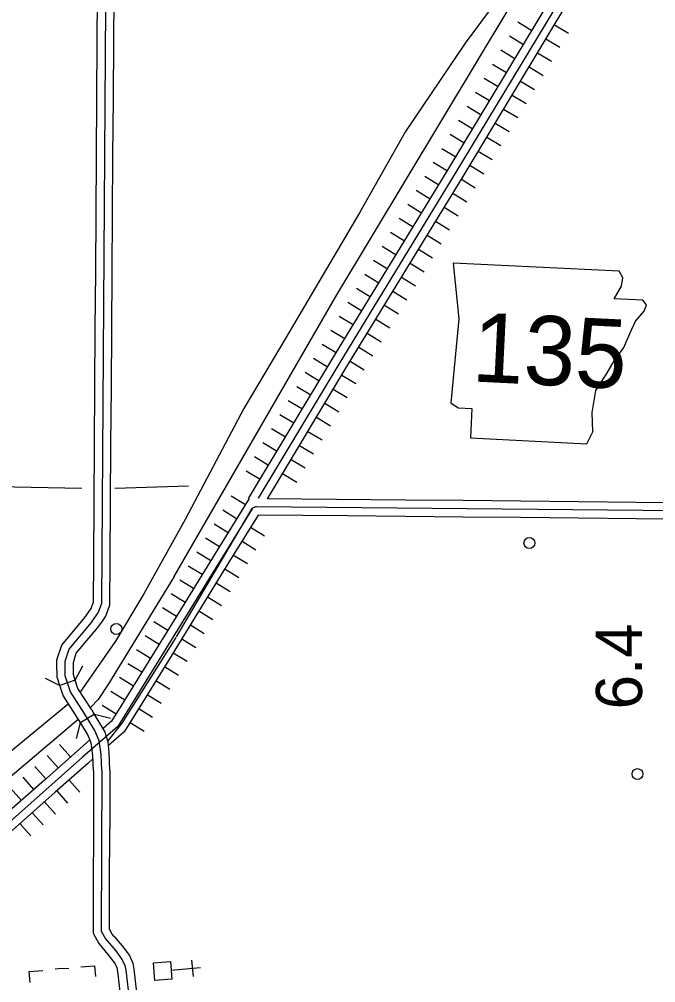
# Model space of a CAD drawing. Extents: x -4306 to 3843, y 131 to 8341.
# Drawn here: x -2104 to -1173, y 5516 to 6927 of the extents above; entities that cross this region are included whole.
import ezdxf

# ---------------------------------------------------------------- set-up
doc = ezdxf.new("R2010")
doc.units = 0
for name, color, linetype in [('21', 7, 'Continuous'), ('31', 7, 'Continuous'), ('32', 7, 'Continuous'), ('38', 7, 'Continuous'), ('46', 7, 'Continuous'), ('52', 7, 'Continuous'), ('56', 7, 'Continuous'), ('57', 7, 'Continuous'), ('58', 7, 'Continuous'), ('61', 7, 'Continuous'), ('63', 7, 'Continuous')]:
    doc.layers.add(name, color=color, linetype=linetype)

msp = doc.modelspace()

# ---------------------------------------------------------------- linework, layer by layer
at = {"layer": '21'}
msp.add_lwpolyline([(-1469.2, 6570), (-1461, 6488.3), (-1472.4, 6365.5), (-1461.9, 6358.2), (-1441.6, 6357.2), (-1443.8, 6314), (-1273.4, 6305.6), (-1264.4, 6322.8), (-1265.8, 6351.3), (-1260.1, 6383.6), (-1244, 6408.5), (-1233.6, 6427), (-1219.1, 6446.6), (-1209.9, 6467.9), (-1202.3, 6485.1), (-1189.4, 6499.4), (-1186.2, 6508.7), (-1191.3, 6515.7), (-1233.2, 6517.8), (-1222.8, 6536.2), (-1220.9, 6548.4), (-1226, 6558)], close=True, dxfattribs=at)
at = {"layer": '31'}
for p, q in [((-2022.2, 5959.2), (-2045, 5951.7)), ((-2018.3, 5947.4), (-2022.2, 5959.2)), ((-2040.1, 5936.9), (-2045, 5951.7)), ((-1998, 5916.1), (-2018.3, 5947.4)), ((-2018.3, 5903.4), (-2040.1, 5936.9)), ((-1995.9, 5912.6), (-1998, 5916.1)), ((-1979.1, 5884.4), (-1995.9, 5912.6)), ((-2016.5, 5900.3), (-2018.3, 5903.4)), ((-2004.5, 5880.1), (-2016.5, 5900.3)), ((-1994.1, 5909.4), (-2014.7, 5897.1)), ((-1974.2, 5868.6), (-1979.1, 5884.4)), ((-1999.1, 5867.4), (-2004.5, 5880.1)), ((-1972.7, 5854.1), (-1974.2, 5868.6)), ((-1996.5, 5849.2), (-1999.1, 5867.4)), ((-1971.5, 5827.4), (-1972.7, 5854.1)), ((-1995.5, 5826.4), (-1996.5, 5849.2)), ((-1995.5, 5827), (-1995.8, 5742.5)), ((-1971.5, 5826.9), (-1971.8, 5742.4)), ((-1971.8, 5742.4), (-1971.8, 5742.4)), ((-1965.3, 5584.1), (-1953.7, 5570.5)), ((-1983.6, 5568.6), (-1972.5, 5555.5)), ((-1953.7, 5570.5), (-1942.9, 5556.2)), ((-1972.5, 5555.5), (-1963.8, 5543.9)), ((-1963.8, 5543.9), (-1961.2, 5538.2)), ((-1942.9, 5556.2), (-1938, 5545.2)), ((-1938, 5545.2), (-1936.5, 5536.3)), ((-1961.2, 5538.2), (-1960.3, 5532.9)), ((-1960.3, 5532.9), (-1956.3, 5499)), ((-1936.5, 5536.3), (-1932.4, 5501.9))]:
    msp.add_line(p, q, dxfattribs=at)
for points in [[(-1995.8, 5742.5), (-1996, 5658)], [(-1972, 5657.9), (-1971.8, 5742.4)], [(-1996, 5658), (-1996.2, 5588.8), (-1987.9, 5573.7), (-1983.6, 5568.6)], [(-1965.3, 5584.1), (-1968, 5587.4), (-1972.2, 5595), (-1972, 5657.9)]]:
    msp.add_lwpolyline(points, dxfattribs=at)
at = {"layer": '32'}
for p, q in [((-1281.6, 7007.3), (-1466.4, 6700.5)), ((-1990, 6895.6), (-1989.4, 6980)), ((-1966, 6895.4), (-1965.4, 6979.9)), ((-1990.5, 6811.1), (-1990, 6895.6)), ((-1966.5, 6810.9), (-1966, 6895.4)), ((-1991.1, 6726.6), (-1990.5, 6811.1)), ((-1967.1, 6726.4), (-1966.5, 6810.9)), ((-1991.7, 6642.1), (-1991.1, 6726.6)), ((-1967.7, 6641.9), (-1967.1, 6726.4)), ((-1466.4, 6700.5), (-1634.9, 6424.7)), ((-1992.3, 6557.6), (-1991.7, 6642.1)), ((-1968.3, 6557.4), (-1967.7, 6641.9)), ((-1992.9, 6473.1), (-1992.3, 6557.6)), ((-1968.9, 6473), (-1968.3, 6557.4)), ((-1993.4, 6388.6), (-1992.9, 6473.1)), ((-1969.4, 6388.5), (-1968.9, 6473)), ((-1634.9, 6424.7), (-1754.5, 6225.6)), ((-1994, 6304.2), (-1993.4, 6388.6)), ((-1970, 6304), (-1969.4, 6388.5)), ((-1994.6, 6219.7), (-1994, 6304.2)), ((-1970.6, 6219.5), (-1970, 6304)), ((-1767.9, 6225.3), (-1817.7, 6144.6)), ((-1539, 6223), (-1740.8, 6225)), ((-1454.5, 6222.2), (-1539, 6223)), ((-1370.1, 6221.4), (-1454.5, 6222.2)), ((-1285.6, 6220.5), (-1370.1, 6221.4)), ((-1995.2, 6135.2), (-1994.6, 6219.7)), ((-1971.2, 6135), (-1970.6, 6219.5)), ((-1763.1, 6210.2), (-1959.8, 5891.5)), ((-1763.1, 6210.2), (-1959.8, 5891.5)), ((-1763.8, 6210.7), (-1874.4, 6022.8)), ((-1758.3, 6213), (-1763.8, 6210.7)), ((-1756.9, 6213.2), (-1758.3, 6213)), ((-271.9, 6198.6), (-1756.9, 6213.2)), ((-1201.1, 6219.7), (-1285.6, 6220.5)), ((-1116.6, 6218.9), (-1201.1, 6219.7)), ((-1754.6, 6201.1), (-1797.3, 6132)), ((-1623.8, 6199.9), (-1754.6, 6201.1)), ((-1539.3, 6199), (-1623.8, 6199.9)), ((-1454.8, 6198.2), (-1539.3, 6199)), ((-1370.3, 6197.4), (-1454.8, 6198.2)), ((-1285.8, 6196.5), (-1370.3, 6197.4)), ((-1201.3, 6195.7), (-1285.8, 6196.5)), ((-1116.8, 6194.9), (-1201.3, 6195.7)), ((-1817.7, 6144.6), (-1862.1, 6072.7)), ((-1995.6, 6074), (-1995.2, 6135.2)), ((-1971.6, 6069.8), (-1971.2, 6135)), ((-1797.3, 6132), (-1841.7, 6060.1)), ((-1999, 6064.4), (-1995.6, 6074)), ((-1977.5, 6053.3), (-1971.6, 6069.8)), ((-1862.1, 6072.7), (-1906.5, 6000.8)), ((-2008.2, 6051.2), (-2002.3, 6059.6)), ((-2002.3, 6059.6), (-1999, 6064.4)), ((-1982.6, 6045.9), (-1977.5, 6053.3)), ((-1841.7, 6060.1), (-1886, 5988.2)), ((-2042.1, 6010.7), (-2008.2, 6051.2)), ((-1989.1, 6036.6), (-1982.6, 6045.9)), ((-2020.7, 5998.9), (-1989.1, 6036.6)), ((-2049, 5989), (-2042.1, 6010.7)), ((-1875, 6021.7), (-1954.3, 5896.3)), ((-2025, 5985.3), (-2020.7, 5998.9)), ((-1906.5, 6000.8), (-1950.9, 5928.9)), ((-2049, 5982.9), (-2049, 5989)), ((-2048.9, 5963.7), (-2049, 5982.9)), ((-2025, 5983), (-2025, 5985.3)), ((-2024.9, 5967.6), (-2025, 5983)), ((-1886, 5988.2), (-1930.4, 5916.3)), ((-2022.2, 5959.2), (-2024.9, 5967.6)), ((-2045, 5951.7), (-2048.9, 5963.7)), ((-1950.9, 5928.9), (-1969.1, 5899.4)), ((-1930.4, 5916.3), (-1950.6, 5883.7)), ((-1969.1, 5899.4), (-1981.6, 5888.6)), ((-1954.3, 5896.3), (-1975.2, 5870.1)), ((-1959.8, 5891.5), (-2011.8, 5846.5)), ((-1959.8, 5891.5), (-2011.8, 5846.5)), ((-1950.6, 5883.7), (-1973.7, 5863.7)), ((-2001, 5871.8), (-2019.7, 5855.6)), ((-2019.7, 5855.6), (-2067.4, 5813.2)), ((-2011.8, 5846.5), (-2341.9, 5553.6)), ((-2011.8, 5846.5), (-2341.9, 5553.6)), ((-1996.3, 5844.1), (-2003.9, 5837.5)), ((-2003.9, 5837.5), (-2051.5, 5795.3)), ((-2067.4, 5813.2), (-2130.6, 5757.2)), ((-2051.5, 5795.3), (-2114.7, 5739.2))]:
    msp.add_line(p, q, dxfattribs=at)
for points in [[(-1983.6, 6071.9), (-1976.6, 7092.7)], [(-1983.5, 5826.9), (-1984.5, 5850.4), (-1987.5, 5870.6), (-1993.7, 5885.5), (-2008.1, 5909.8), (-2029.2, 5942.1), (-2036.9, 5965.7), (-2037, 5987.2), (-2031.4, 6004.8), (-1998.6, 6043.9), (-1988.2, 6058.8), (-1983.6, 6071.9)], [(-1983.5, 5826.9), (-1984.2, 5591.9), (-1978, 5580.6), (-1963.1, 5563), (-1953.4, 5550.1), (-1949.6, 5541.7), (-1948.4, 5534.6), (-1931.5, 5392.4), (-1927.1, 4704.6), (-1924.6, 4492.3), (-1929.1, 4070.4), (-1927.7, 3649.7), (-1928.3, 3227.1), (-1927.2, 3133.3)]]:
    msp.add_lwpolyline(points, dxfattribs=at)
at = {"layer": '38'}
for p, q in [((-2022.2, 5959.2), (-2011.4, 5980.6)), ((-2066.4, 5962.5), (-2045, 5951.7)), ((-2033.6, 5955.4), (-2033.6, 5955.4))]:
    msp.add_line(p, q, dxfattribs=at)
for points in [[(-2020.6, 5873.8), (-2014.7, 5897.1)], [(-1994.1, 5909.4), (-1970.8, 5903.5)]]:
    msp.add_lwpolyline(points, dxfattribs=at)
at = {"layer": '46'}
for p, q in [((-1476.6, 6706.8), (-1269.2, 7051.3)), ((-1456.1, 6694.3), (-1241.5, 7050.7)), ((-1645.2, 6430.9), (-1476.6, 6706.8)), ((-1624.7, 6418.4), (-1456.1, 6694.3)), ((-1768.7, 6225.3), (-1645.2, 6430.9)), ((-1740.8, 6225), (-1624.7, 6418.4))]:
    msp.add_line(p, q, dxfattribs=at)
at = {"layer": '52'}
for p, q in [((-2012.6, 6240.1), (-2463.1, 6248)), ((-1856.6, 6243.4), (-1964.4, 6240.1))]:
    msp.add_line(p, q, dxfattribs=at)
at = {"layer": '56'}
for points in [[(-1330.4, 7050.5), (-1406.5, 6952.3), (-1451.4, 6892.2), (-1538.8, 6762.8), (-1606.3, 6643.7), (-1713.9, 6460.4), (-1775.4, 6357), (-1861.2, 6194.6), (-1921.7, 6085.7), (-1963.4, 6016.6), (-2014.8, 5943)], [(-1877.3, 6111.1), (-1639.5, 6523.5), (-1385.4, 6945.6), (-1310.2, 7047.2)], [(-1877.3, 6111.1), (-1973.4, 5953.9), (-1988.6, 5931.1), (-1999.6, 5920)], [(-2398.5, 6031.6), (-2398.3, 6037), (-2395, 6040.1), (-2389.7, 6035.4), (-2388.7, 6026.5), (-2387.2, 6010.6), (-2387.6, 6008.6), (-2433.2, 5624.8), (-2429.8, 5610.9), (-2427.3, 5606.7), (-2422.5, 5606.4), (-2411.6, 5612.3), (-2032.7, 5924.6)], [(-2017.9, 5901.6), (-2420, 5561.3)]]:
    msp.add_lwpolyline(points, dxfattribs=at)
at = {"layer": '57'}
for centre in [(-1357.4, 6160.2), (-1962.1, 6034.3), (-1199.2, 5821.9)]:
    msp.add_circle(centre, 8, dxfattribs=at)
at = {"layer": '58'}
for p, q in [((-1852, 5549.2), (-1849.9, 5525.3)), ((-2041.8, 5537), (-2051.6, 5536.1)), ((-2041.8, 5537), (-2031.7, 5537.9)), ((-1839, 5538.3), (-1881.9, 5534.5))]:
    msp.add_line(p, q, dxfattribs=at)
msp.add_lwpolyline([(-1907.9, 5545.3), (-1883, 5547.5), (-1880.8, 5521.7), (-1905.6, 5519.5)], close=True, dxfattribs=at)
for points in [[(-2088.2, 5516.7), (-2089.6, 5532.7), (-2069.7, 5534.5)], [(-2013.9, 5539.5), (-1994, 5541.3), (-1992.6, 5525.3)]]:
    msp.add_lwpolyline(points, dxfattribs=at)
at = {"layer": '63'}
for p, q in [((-1374.4, 6923.1), (-1353.8, 6910.7)), ((-1320.9, 6918.9), (-1300.3, 6906.5)), ((-1386.8, 6902.5), (-1366.2, 6890.2)), ((-1386.8, 6902.5), (-1366.2, 6890.2)), ((-1333.2, 6898.3), (-1312.7, 6885.9)), ((-1399.1, 6882), (-1378.6, 6869.6)), ((-1345.6, 6877.8), (-1325.1, 6865.4)), ((-1345.6, 6877.8), (-1325.1, 6865.4)), ((-1411.5, 6861.4), (-1391, 6849)), ((-1358, 6857.2), (-1337.5, 6844.8)), ((-1423.9, 6840.9), (-1403.3, 6828.5)), ((-1423.9, 6840.9), (-1403.3, 6828.5)), ((-1370.4, 6836.6), (-1349.8, 6824.3)), ((-1436.3, 6820.3), (-1415.7, 6807.9)), ((-1382.8, 6816.1), (-1362.2, 6803.7)), ((-1382.8, 6816.1), (-1362.2, 6803.7)), ((-1448.7, 6799.7), (-1428.1, 6787.3)), ((-1395.2, 6795.5), (-1374.6, 6783.1)), ((-1461.1, 6779.2), (-1440.5, 6766.8)), ((-1461.1, 6779.2), (-1440.5, 6766.8)), ((-1407.5, 6775), (-1387, 6762.6)), ((-1473.4, 6758.6), (-1452.9, 6746.2)), ((-1419.9, 6754.4), (-1399.4, 6742)), ((-1419.9, 6754.4), (-1399.4, 6742)), ((-1485.8, 6738), (-1465.3, 6725.7)), ((-1432.3, 6733.8), (-1411.8, 6721.5)), ((-1498.1, 6717.7), (-1477.6, 6705.2)), ((-1498.1, 6717.7), (-1477.6, 6705.2)), ((-1444.7, 6713.3), (-1424.1, 6700.9)), ((-1510.6, 6697.2), (-1490.1, 6684.7)), ((-1457.1, 6692.7), (-1436.7, 6680.1)), ((-1457.1, 6692.7), (-1436.7, 6680.1)), ((-1523.1, 6676.7), (-1502.6, 6664.2)), ((-1469.6, 6672.2), (-1449.2, 6659.7)), ((-1535.6, 6656.2), (-1515.2, 6643.7)), ((-1535.6, 6656.2), (-1515.2, 6643.7)), ((-1482.2, 6651.7), (-1461.7, 6639.2)), ((-1548.2, 6635.8), (-1527.7, 6623.2)), ((-1494.7, 6631.2), (-1474.2, 6618.7)), ((-1494.7, 6631.2), (-1474.2, 6618.7)), ((-1560.7, 6615.3), (-1540.2, 6602.8)), ((-1507.2, 6610.7), (-1486.7, 6598.2)), ((-1573.2, 6594.8), (-1552.7, 6582.3)), ((-1573.2, 6594.8), (-1552.7, 6582.3)), ((-1519.7, 6590.2), (-1499.2, 6577.7)), ((-1585.7, 6574.3), (-1565.2, 6561.8)), ((-1532.2, 6569.8), (-1511.7, 6557.3)), ((-1532.2, 6569.8), (-1511.7, 6557.3)), ((-1598.2, 6553.8), (-1577.7, 6541.3)), ((-1544.7, 6549.3), (-1524.2, 6536.8)), ((-1610.7, 6533.3), (-1590.2, 6520.8)), ((-1610.7, 6533.3), (-1590.2, 6520.8)), ((-1557.2, 6528.8), (-1536.8, 6516.3)), ((-1623.2, 6512.9), (-1602.8, 6500.3)), ((-1569.8, 6508.3), (-1549.3, 6495.8)), ((-1569.8, 6508.3), (-1549.3, 6495.8)), ((-1635.8, 6492.4), (-1615.3, 6479.9)), ((-1582.3, 6487.8), (-1561.8, 6475.3)), ((-1648.3, 6471.9), (-1627.8, 6459.4)), ((-1648.3, 6471.9), (-1627.8, 6459.4)), ((-1594.8, 6467.4), (-1574.3, 6454.8)), ((-1660.8, 6451.4), (-1640.3, 6438.9)), ((-1607.3, 6446.9), (-1586.8, 6434.4)), ((-1607.3, 6446.9), (-1586.8, 6434.4)), ((-1673.3, 6430.6), (-1652.8, 6418.3)), ((-1619.8, 6426.4), (-1599.3, 6413.9)), ((-1685.7, 6410.1), (-1665.1, 6397.7)), ((-1685.7, 6410.1), (-1665.1, 6397.7)), ((-1632.2, 6405.9), (-1611.6, 6393.6)), ((-1698.1, 6389.5), (-1677.5, 6377.1)), ((-1644.5, 6385.3), (-1624, 6373)), ((-1644.5, 6385.3), (-1624, 6373)), ((-1710.4, 6368.9), (-1689.8, 6356.5)), ((-1656.9, 6364.8), (-1636.3, 6352.4)), ((-1722.8, 6348.3), (-1702.2, 6336)), ((-1722.8, 6348.3), (-1702.2, 6336)), ((-1669.3, 6344.2), (-1648.7, 6331.8)), ((-1735.1, 6327.8), (-1714.5, 6315.4)), ((-1681.6, 6323.6), (-1661, 6311.3)), ((-1681.6, 6323.6), (-1661, 6311.3)), ((-1747.5, 6307.2), (-1726.9, 6294.8)), ((-1694, 6303), (-1673.4, 6290.7)), ((-1759.8, 6286.6), (-1739.3, 6274.2)), ((-1759.8, 6286.6), (-1739.3, 6274.2)), ((-1706.3, 6282.5), (-1685.7, 6270.1)), ((-1772.2, 6266), (-1751.6, 6253.7)), ((-1718.7, 6261.9), (-1698.1, 6249.5)), ((-1718.7, 6261.9), (-1698.1, 6249.5)), ((-1793.8, 6229.1), (-1773.3, 6216.5)), ((-1806.4, 6208.7), (-1786, 6196.1)), ((-1819, 6188.2), (-1798.6, 6175.6)), ((-1765.5, 6183.5), (-1745.1, 6170.9)), ((-1831.6, 6167.8), (-1811.2, 6155.2)), ((-1831.6, 6167.8), (-1811.2, 6155.2)), ((-1778.1, 6163), (-1757.7, 6150.4)), ((-1844.2, 6147.4), (-1823.8, 6134.8)), ((-1790.7, 6142.6), (-1770.3, 6130)), ((-1790.7, 6142.6), (-1770.3, 6130)), ((-1856.8, 6127), (-1836.4, 6114.4)), ((-1803.3, 6122.2), (-1782.9, 6109.6)), ((-1869.4, 6106.5), (-1849, 6093.9)), ((-1869.4, 6106.5), (-1849, 6093.9)), ((-1816, 6101.8), (-1795.5, 6089.1)), ((-1882, 6086.1), (-1861.6, 6073.5)), ((-1828.6, 6081.3), (-1808.1, 6068.7)), ((-1828.6, 6081.3), (-1808.1, 6068.7)), ((-1894.6, 6065.7), (-1874.2, 6053.1)), ((-1841.2, 6060.9), (-1820.7, 6048.3)), ((-1907.2, 6045.3), (-1886.8, 6032.7)), ((-1907.2, 6045.3), (-1886.8, 6032.7)), ((-1853.8, 6040.5), (-1833.4, 6027.9)), ((-1919.8, 6024.8), (-1899.4, 6012.2)), ((-1866.4, 6020.1), (-1846, 6007.4)), ((-1866.4, 6020.1), (-1846, 6007.4)), ((-1932.4, 6004.4), (-1912, 5991.8)), ((-1879, 5999.6), (-1858.6, 5987)), ((-1945.1, 5984), (-1924.6, 5971.4)), ((-1945.1, 5984), (-1924.6, 5971.4)), ((-1891.6, 5979.2), (-1871.2, 5966.6)), ((-1957.7, 5963.6), (-1937.2, 5951)), ((-1904.2, 5958.8), (-1883.8, 5946.2)), ((-1904.2, 5958.8), (-1883.8, 5946.2)), ((-1970.3, 5943.1), (-1949.8, 5930.5)), ((-1916.8, 5938.4), (-1896.4, 5925.7)), ((-1982.9, 5922.7), (-1962.4, 5910.1)), ((-1929.4, 5917.9), (-1909, 5905.3)), ((-1942, 5897.5), (-1921.6, 5884.9)), ((-1942, 5897.5), (-1921.6, 5884.9)), ((-2045.3, 5865), (-2029.4, 5847)), ((-2063.2, 5849), (-2047.3, 5831.1)), ((-2081.2, 5833.1), (-2065.3, 5815.1)), ((-2081.2, 5833.1), (-2065.3, 5815.1)), ((-2099.2, 5817.2), (-2083.2, 5799.2)), ((-2031.4, 5813.1), (-2015.5, 5795.2)), ((-2117.1, 5801.2), (-2101.2, 5783.3)), ((-2049.3, 5797.2), (-2033.4, 5779.2)), ((-2049.3, 5797.2), (-2033.4, 5779.2)), ((-2067.3, 5781.3), (-2051.4, 5763.3)), ((-2085.3, 5765.3), (-2069.3, 5747.4)), ((-2103.2, 5749.4), (-2087.3, 5731.4)), ((-2103.2, 5749.4), (-2087.3, 5731.4))]:
    msp.add_line(p, q, dxfattribs=at)

# ---------------------------------------------------------------- texts
at = {"layer": '21'}
msp.add_text('135', height=101.29, rotation=357.2006, dxfattribs=at).set_placement((-1442.8, 6396.8))
at = {"layer": '61'}
msp.add_text('6.4', height=67.59, rotation=90.1036, dxfattribs=at).set_placement((-1192.5, 5916.7))

doc.saveas('drawing.dxf')
